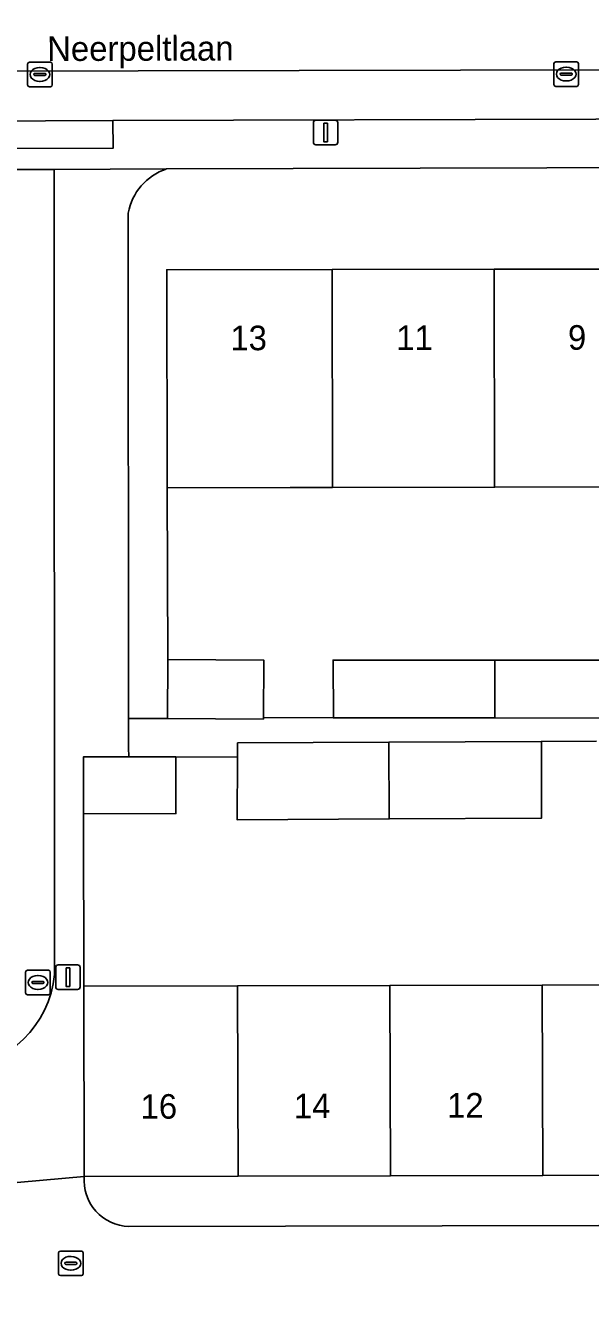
# Model space of a CAD drawing. Extents: x 160732 to 162107, y 387428 to 388479.
# Drawn here: x 161218.5 to 161241.5, y 388003.2 to 388054.8 of the extents above; entities that cross this region are included whole.
import ezdxf

# ---------------------------------------------------------------- set-up
doc = ezdxf.new("R2010")
doc.units = 0
for name, color, linetype in [('IMGEO_Brandkraan', 7, 'Continuous'), ('IMGEO_Erf', 7, 'Continuous'), ('IMGEO_Kolk', 7, 'Continuous'), ('IMGEO_Lichtmast', 7, 'Continuous'), ('IMGEO_Muur', 7, 'Continuous'), ('IMGEO_Openbare_ruimte_label', 7, 'Continuous'), ('IMGEO_Pand', 7, 'Continuous'), ('IMGEO_Pand_nummerreeks', 7, 'Continuous'), ('IMGEO_Parkeervlak_open', 7, 'Continuous'), ('IMGEO_Rijbaan_lokaal_open', 7, 'Continuous'), ('IMGEO_Rioolput', 7, 'Continuous'), ('IMGEO_Voetpad_open', 7, 'Continuous')]:
    doc.layers.add(name, color=color, linetype=linetype)

msp = doc.modelspace()

# ---------------------------------------------------------------- linework, layer by layer
at = {"layer": 'IMGEO_Brandkraan'}
for p, q in [((161219.843, 388003.983), (161219.843, 388004.835)), ((161219.918, 388004.909), (161220.77, 388004.909)), ((161220.331, 388004.689), (161220.356, 388004.689)), ((161220.844, 388004.835), (161220.844, 388003.983)), ((161220.102, 388004.403), (161220.102, 388004.415)), ((161220.54, 388004.366), (161220.142, 388004.366)), ((161220.145, 388004.452), (161220.543, 388004.452)), ((161220.354, 388004.129), (161220.329, 388004.129)), ((161220.586, 388004.415), (161220.586, 388004.403)), ((161220.77, 388003.909), (161219.918, 388003.909))]:
    msp.add_line(p, q, dxfattribs=at)
for points in [[(161219.843, 388003.983), (161219.843, 388004.835)], [(161219.918, 388004.909), (161220.77, 388004.909)], [(161220.844, 388004.835), (161220.844, 388003.983)], [(161220.77, 388003.909), (161219.918, 388003.909)]]:
    msp.add_lwpolyline(points, dxfattribs=at)
for centre, radius, start, end in [((161219.92, 388004.833), 0.0765, 91.552, 178.448), ((161219.92, 388004.833), 0.0765, 91.552, 178.448), ((161220.768, 388004.833), 0.0765, 1.552, 88.448), ((161220.768, 388004.833), 0.0765, 1.552, 88.448), ((161219.92, 388003.985), 0.0765, 181.552, 268.448), ((161219.92, 388003.985), 0.0765, 181.552, 268.448), ((161220.142, 388004.412), 0.0403, 85.8775, 175.7526), ((161220.139, 388004.402), 0.0366, 178.938, 274.7102), ((161220.543, 388004.409), 0.043, 264.8664, 352.4533), ((161220.547, 388004.414), 0.0386, 1.7309, 96.639), ((161220.768, 388003.985), 0.0765, 271.552, 358.448), ((161220.768, 388003.985), 0.0765, 271.552, 358.448)]:
    msp.add_arc(centre, radius, start, end, dxfattribs=at)
for centre, major_axis, ratio, start_param, end_param in [((161220.33, 388004.409), (-0.387, 0.002), 0.722429, 4.712389, 7.853982), ((161220.355, 388004.409), (-0.39, 0.002), 0.717154, 1.570796, 4.712389)]:
    msp.add_ellipse(centre, major_axis=major_axis, ratio=ratio, start_param=start_param, end_param=end_param, dxfattribs=at)
at = {"layer": 'IMGEO_Erf'}
for points in [[(161270.702, 388036.055), (161263.977, 388036.045), (161257.377, 388036.035), (161250.777, 388036.025), (161244.178, 388036.015), (161237.578, 388036.005), (161230.978, 388035.995), (161229.256, 388035.992), (161224.256, 388035.984), (161224.242, 388044.855), (161230.965, 388044.865), (161237.565, 388044.876), (161244.165, 388044.886), (161250.764, 388044.896), (161257.364, 388044.906), (161263.964, 388044.917), (161270.689, 388044.927), (161270.677, 388049.09), (161224.221, 388048.959)], [(161222.674, 388047.165), (161222.685, 388026.588), (161224.275, 388026.589), (161224.289, 388028.988), (161228.187, 388028.965), (161228.173, 388026.628), (161231.018, 388026.611), (161231.006, 388028.964), (161237.588, 388028.961), (161244.188, 388028.958), (161250.787, 388028.955), (161257.387, 388028.952), (161263.987, 388028.95), (161270.675, 388028.947), (161270.702, 388036.055)], [(161241.724, 388025.667), (161239.479, 388025.655), (161239.49, 388022.531), (161233.29, 388022.5), (161227.1, 388022.469), (161227.12, 388025.013), (161224.61, 388025.032), (161224.616, 388022.718), (161220.858, 388022.708), (161220.866, 388015.69), (161227.114, 388015.704), (161233.314, 388015.718), (161239.514, 388015.731), (161245.714, 388015.745)], [(161270.732, 388008.051), (161264.341, 388008.037), (161258.141, 388008.023), (161251.941, 388008.01), (161245.741, 388007.996), (161239.541, 388007.982), (161233.341, 388007.968), (161227.141, 388007.954), (161220.883, 388007.94)], [(161222.696, 388005.905), (161248.184, 388005.966), (161270.656, 388006.02), (161270.737, 388006.02), (161270.732, 388008.051)]]:
    msp.add_lwpolyline(points, dxfattribs=at)
for centre, radius, start, end in [((161224.97, 388046.749), 2.333, 108.7246, 169.7318), ((161222.77, 388007.796), 1.892, 175.6326, 267.7637)]:
    msp.add_arc(centre, radius, start, end, dxfattribs=at)
at = {"layer": 'IMGEO_Kolk'}
for p, q in [((161239.989, 388052.397), (161239.989, 388053.249)), ((161240.064, 388053.323), (161240.916, 388053.323)), ((161240.477, 388053.103), (161240.502, 388053.103)), ((161240.99, 388053.249), (161240.99, 388052.397)), ((161240.248, 388052.817), (161240.248, 388052.829)), ((161240.686, 388052.78), (161240.288, 388052.78)), ((161240.291, 388052.866), (161240.689, 388052.866)), ((161240.5, 388052.543), (161240.475, 388052.543)), ((161240.732, 388052.829), (161240.732, 388052.817)), ((161240.916, 388052.323), (161240.064, 388052.323))]:
    msp.add_line(p, q, dxfattribs=at)
for points in [[(161239.989, 388052.397), (161239.989, 388053.249)], [(161240.064, 388053.323), (161240.916, 388053.323)], [(161240.99, 388053.249), (161240.99, 388052.397)], [(161240.916, 388052.323), (161240.064, 388052.323)]]:
    msp.add_lwpolyline(points, dxfattribs=at)
for centre, radius, start, end in [((161240.066, 388053.247), 0.0765, 91.552, 178.448), ((161240.066, 388053.247), 0.0765, 91.552, 178.448), ((161240.914, 388053.247), 0.0765, 1.552, 88.448), ((161240.914, 388053.247), 0.0765, 1.552, 88.448), ((161240.288, 388052.826), 0.0403, 85.8775, 175.7526), ((161240.285, 388052.816), 0.0366, 178.938, 274.7102), ((161240.689, 388052.823), 0.043, 264.8664, 352.4533), ((161240.693, 388052.828), 0.0386, 1.7309, 96.639), ((161240.066, 388052.399), 0.0765, 181.552, 268.448), ((161240.066, 388052.399), 0.0765, 181.552, 268.448), ((161240.914, 388052.399), 0.0765, 271.552, 358.448), ((161240.914, 388052.399), 0.0765, 271.552, 358.448)]:
    msp.add_arc(centre, radius, start, end, dxfattribs=at)
for centre, major_axis, ratio, start_param, end_param in [((161240.476, 388052.823), (-0.387, 0.002), 0.722429, 4.712389, 7.853982), ((161240.501, 388052.823), (-0.39, 0.002), 0.717154, 1.570796, 4.712389)]:
    msp.add_ellipse(centre, major_axis=major_axis, ratio=ratio, start_param=start_param, end_param=end_param, dxfattribs=at)
at = {"layer": 'IMGEO_Lichtmast'}
for p, q in [((161230.308, 388050.945), (161231.098, 388050.945)), ((161231.098, 388050.945), (161230.308, 388050.945)), ((161230.208, 388050.045), (161230.208, 388050.845)), ((161230.208, 388050.845), (161230.208, 388050.045)), ((161231.198, 388050.845), (161231.198, 388050.045)), ((161231.198, 388050.045), (161231.198, 388050.845)), ((161231.098, 388049.945), (161230.308, 388049.945)), ((161230.308, 388049.945), (161231.098, 388049.945)), ((161219.727, 388015.658), (161219.727, 388016.458)), ((161219.727, 388016.458), (161219.727, 388015.658)), ((161219.827, 388016.558), (161220.617, 388016.558)), ((161220.617, 388016.558), (161219.827, 388016.558)), ((161220.717, 388016.458), (161220.717, 388015.658)), ((161220.717, 388015.658), (161220.717, 388016.458)), ((161220.617, 388015.558), (161219.827, 388015.558)), ((161219.827, 388015.558), (161220.617, 388015.558))]:
    msp.add_line(p, q, dxfattribs=at)
for points in [[(161230.628, 388050.82), (161230.778, 388050.82), (161230.778, 388050.07), (161230.628, 388050.07), (161230.628, 388050.82)], [(161220.147, 388016.433), (161220.297, 388016.433), (161220.297, 388015.683), (161220.147, 388015.683), (161220.147, 388016.433)]]:
    msp.add_lwpolyline(points, dxfattribs=at)
for centre, start, end in [((161230.308, 388050.845), 90, 180), ((161230.308, 388050.845), 90, 180), ((161231.098, 388050.845), 0, 90), ((161231.098, 388050.845), 360, 90), ((161230.308, 388050.045), 180, 270), ((161230.308, 388050.045), 180, 270), ((161231.098, 388050.045), 270, 0), ((161231.098, 388050.045), 270, 0), ((161219.827, 388016.458), 90, 180), ((161219.827, 388016.458), 90, 180), ((161220.617, 388016.458), 0, 90), ((161220.617, 388016.458), 360, 90), ((161219.827, 388015.658), 180, 270), ((161219.827, 388015.658), 180, 270), ((161220.617, 388015.658), 270, 0), ((161220.617, 388015.658), 270, 0)]:
    msp.add_arc(centre, 0.1, start, end, dxfattribs=at)
at = {"layer": 'IMGEO_Muur'}
for points in [[(161224.256, 388035.984), (161224.289, 388028.988)], [(161220.858, 388022.708), (161220.866, 388015.69)]]:
    msp.add_lwpolyline(points, dxfattribs=at)
at = {"layer": 'IMGEO_Pand'}
for points in [[(161224.242, 388044.855), (161224.256, 388035.984), (161229.256, 388035.992), (161230.978, 388035.995), (161230.965, 388044.865)], [(161237.565, 388044.876), (161230.965, 388044.865), (161230.978, 388035.995), (161237.578, 388036.005)], [(161237.578, 388036.005), (161244.178, 388036.015), (161244.165, 388044.886), (161237.565, 388044.876)], [(161228.187, 388028.965), (161224.289, 388028.988), (161224.275, 388026.589), (161228.173, 388026.565), (161228.173, 388026.628)], [(161237.592, 388026.609), (161237.588, 388028.961), (161231.006, 388028.964), (161231.018, 388026.611)], [(161244.192, 388026.606), (161244.188, 388028.958), (161237.588, 388028.961), (161237.592, 388026.609)], [(161239.49, 388022.531), (161239.479, 388025.655), (161233.279, 388025.624), (161233.29, 388022.5)], [(161233.279, 388025.624), (161227.124, 388025.593), (161227.12, 388025.013), (161227.1, 388022.469), (161233.29, 388022.5)], [(161220.858, 388022.708), (161224.616, 388022.718), (161224.61, 388025.032), (161222.702, 388025.027), (161220.852, 388025.023)], [(161220.866, 388015.69), (161220.883, 388007.94), (161227.141, 388007.954), (161227.114, 388015.704)], [(161227.114, 388015.704), (161227.141, 388007.954), (161233.341, 388007.968), (161233.314, 388015.718)], [(161239.541, 388007.982), (161239.514, 388015.731), (161233.314, 388015.718), (161233.341, 388007.968)], [(161245.741, 388007.996), (161245.714, 388015.745), (161239.514, 388015.731), (161239.541, 388007.982)]]:
    msp.add_lwpolyline(points, close=True, dxfattribs=at)
at = {"layer": 'IMGEO_Parkeervlak_open'}
for points in [[(161293.331, 388053.085), (161265.928, 388053.054), (161262.413, 388053.043), (161170.608, 388052.85)], [(161173.827, 388050.837), (161213.836, 388050.887), (161222.055, 388050.928), (161280.986, 388051.09), (161290.368, 388051.014), (161291.09, 388051.406), (161292.241, 388052.535)]]:
    msp.add_lwpolyline(points, dxfattribs=at)
at = {"layer": 'IMGEO_Rijbaan_lokaal_open'}
msp.add_lwpolyline([(161262.413, 388053.043), (161262.397, 388058.009), (161168.683, 388057.787), (161168.664, 388052.88), (161170.608, 388052.85)], close=True, dxfattribs=at)
msp.add_lwpolyline([(161219.675, 388016.166), (161219.668, 388048.943), (161216.511, 388048.935), (161216.589, 388027.069), (161216.422, 388027.018), (161216.457, 388021.085), (161213.418, 388021.067), (161210.379, 388021.049), (161207.34, 388021.031), (161204.301, 388021.014), (161201.262, 388020.996), (161198.224, 388020.978), (161195.184, 388020.96), (161195.119, 388013.227), (161198.141, 388013.24), (161201.163, 388013.252), (161204.184, 388013.265), (161207.206, 388013.278), (161210.228, 388013.29), (161213.25, 388013.303), (161213.254, 388012.326), (161215.767, 388012.326)], dxfattribs=at)
msp.add_arc((161215.439, 388016.568), 4.255, 274.4192, 354.5751, dxfattribs=at)
at = {"layer": 'IMGEO_Rioolput'}
for p, q in [((161218.583, 388052.381), (161218.583, 388053.233)), ((161218.658, 388053.307), (161219.51, 388053.307)), ((161219.071, 388053.087), (161219.096, 388053.087)), ((161219.584, 388053.233), (161219.584, 388052.381)), ((161218.842, 388052.801), (161218.842, 388052.813)), ((161219.28, 388052.764), (161218.882, 388052.764)), ((161218.885, 388052.85), (161219.283, 388052.85)), ((161219.094, 388052.527), (161219.069, 388052.527)), ((161219.326, 388052.813), (161219.326, 388052.801)), ((161219.51, 388052.307), (161218.658, 388052.307)), ((161218.503, 388015.415), (161218.503, 388016.267)), ((161218.578, 388016.341), (161219.43, 388016.341)), ((161218.762, 388015.835), (161218.762, 388015.847)), ((161218.805, 388015.884), (161219.203, 388015.884)), ((161218.991, 388016.121), (161219.016, 388016.121)), ((161219.246, 388015.847), (161219.246, 388015.835)), ((161219.504, 388016.267), (161219.504, 388015.415)), ((161219.43, 388015.341), (161218.578, 388015.341)), ((161219.2, 388015.798), (161218.802, 388015.798)), ((161219.014, 388015.561), (161218.989, 388015.561))]:
    msp.add_line(p, q, dxfattribs=at)
for points in [[(161218.583, 388052.381), (161218.583, 388053.233)], [(161218.658, 388053.307), (161219.51, 388053.307)], [(161219.584, 388053.233), (161219.584, 388052.381)], [(161219.51, 388052.307), (161218.658, 388052.307)], [(161218.503, 388015.415), (161218.503, 388016.267)], [(161218.578, 388016.341), (161219.43, 388016.341)], [(161219.504, 388016.267), (161219.504, 388015.415)], [(161219.43, 388015.341), (161218.578, 388015.341)]]:
    msp.add_lwpolyline(points, dxfattribs=at)
for centre, radius, start, end in [((161218.66, 388053.231), 0.0765, 91.552, 178.448), ((161218.66, 388053.231), 0.0765, 91.552, 178.448), ((161219.508, 388053.231), 0.0765, 1.552, 88.448), ((161219.508, 388053.231), 0.0765, 1.552, 88.448), ((161218.882, 388052.81), 0.0403, 85.8775, 175.7526), ((161218.879, 388052.8), 0.0366, 178.938, 274.7102), ((161219.283, 388052.807), 0.043, 264.8664, 352.4533), ((161219.287, 388052.812), 0.0386, 1.7309, 96.639), ((161218.66, 388052.383), 0.0765, 181.552, 268.448), ((161218.66, 388052.383), 0.0765, 181.552, 268.448), ((161219.508, 388052.383), 0.0765, 271.552, 358.448), ((161219.508, 388052.383), 0.0765, 271.552, 358.448), ((161218.58, 388016.265), 0.0765, 91.552, 178.448), ((161218.58, 388016.265), 0.0765, 91.552, 178.448), ((161218.802, 388015.844), 0.0403, 85.8775, 175.7526), ((161219.207, 388015.846), 0.0386, 1.7309, 96.639), ((161219.428, 388016.265), 0.0765, 1.552, 88.448), ((161219.428, 388016.265), 0.0765, 1.552, 88.448), ((161218.58, 388015.417), 0.0765, 181.552, 268.448), ((161218.58, 388015.417), 0.0765, 181.552, 268.448), ((161218.799, 388015.834), 0.0366, 178.938, 274.7102), ((161219.203, 388015.841), 0.043, 264.8664, 352.4533), ((161219.428, 388015.417), 0.0765, 271.552, 358.448), ((161219.428, 388015.417), 0.0765, 271.552, 358.448)]:
    msp.add_arc(centre, radius, start, end, dxfattribs=at)
for centre, major_axis, ratio, start_param, end_param in [((161219.07, 388052.807), (-0.387, 0.002), 0.722429, 4.712389, 7.853982), ((161219.095, 388052.807), (-0.39, 0.002), 0.717154, 1.570796, 4.712389), ((161218.99, 388015.841), (-0.387, 0.002), 0.722429, 4.712389, 7.853982), ((161219.015, 388015.841), (-0.39, 0.002), 0.717154, 1.570796, 4.712389)]:
    msp.add_ellipse(centre, major_axis=major_axis, ratio=ratio, start_param=start_param, end_param=end_param, dxfattribs=at)
at = {"layer": 'IMGEO_Voetpad_open'}
for points in [[(161292.241, 388052.535), (161291.09, 388051.406), (161290.368, 388051.014), (161280.986, 388051.09), (161222.055, 388050.928), (161222.058, 388049.802), (161213.839, 388049.782), (161213.836, 388050.887), (161173.827, 388050.837)], [(161169.409, 388048.766), (161213.161, 388048.984), (161216.511, 388048.935), (161219.668, 388048.943), (161224.221, 388048.959), (161270.677, 388049.09), (161272.075, 388049.094), (161292.47, 388049.151)], [(161224.221, 388048.959), (161219.668, 388048.943), (161219.675, 388016.166)], [(161215.767, 388012.326), (161213.254, 388012.326), (161213.255, 388012.113), (161213.381, 388007.464), (161217.385, 388007.635), (161220.883, 388007.94), (161220.866, 388015.69), (161220.858, 388022.708), (161220.852, 388025.023), (161222.702, 388025.027), (161222.686, 388025.406), (161222.685, 388026.588), (161222.674, 388047.165)], [(161244.192, 388026.606), (161237.592, 388026.609), (161231.018, 388026.611), (161228.173, 388026.628), (161228.173, 388026.565), (161224.275, 388026.589), (161222.685, 388026.588), (161222.686, 388025.406), (161222.702, 388025.027), (161224.61, 388025.032), (161227.12, 388025.013), (161227.124, 388025.593), (161233.279, 388025.624), (161239.479, 388025.655), (161241.724, 388025.667)], [(161220.883, 388007.94), (161217.385, 388007.635), (161217.501, 387972.088), (161217.515, 387971.998), (161217.376, 387967.03), (161217.48, 387956.261), (161217.496, 387954.255), (161217.507, 387952.589), (161243.083, 387952.638), (161248.135, 387952.571), (161248.071, 387986.562), (161248.067, 387986.627), (161248.197, 387991.584)], [(161248.197, 387991.584), (161248.16, 388003.396), (161248.184, 388005.966), (161222.696, 388005.905)]]:
    msp.add_lwpolyline(points, dxfattribs=at)
msp.add_lwpolyline([(161213.839, 388049.782), (161222.058, 388049.802), (161222.055, 388050.928), (161213.836, 388050.887)], close=True, dxfattribs=at)
for centre, radius, start, end in [((161224.97, 388046.749), 2.333, 108.7246, 169.7318), ((161215.439, 388016.568), 4.255, 274.4192, 354.5751), ((161222.77, 388007.796), 1.892, 175.6326, 267.7637)]:
    msp.add_arc(centre, radius, start, end, dxfattribs=at)

# ---------------------------------------------------------------- texts
at = {"layer": 'IMGEO_Openbare_ruimte_label'}
msp.add_text('Neerpeltlaan', height=1, rotation=0.1719, dxfattribs=at).set_placement((161219.38, 388053.354))
at = {"layer": 'IMGEO_Pand_nummerreeks'}
for s, rotation, p in [('13', 0.0888, (161226.83, 388041.579)), ('11', 0.0888, (161233.579, 388041.59)), ('9', 0.0888, (161240.561, 388041.601)), ('16', 0.2022, (161223.178, 388010.292)), ('14', 0.2022, (161229.413, 388010.314)), ('12', 0.2022, (161235.644, 388010.336))]:
    msp.add_text(s, height=1, rotation=rotation, dxfattribs=at).set_placement(p)

doc.saveas('drawing.dxf')
